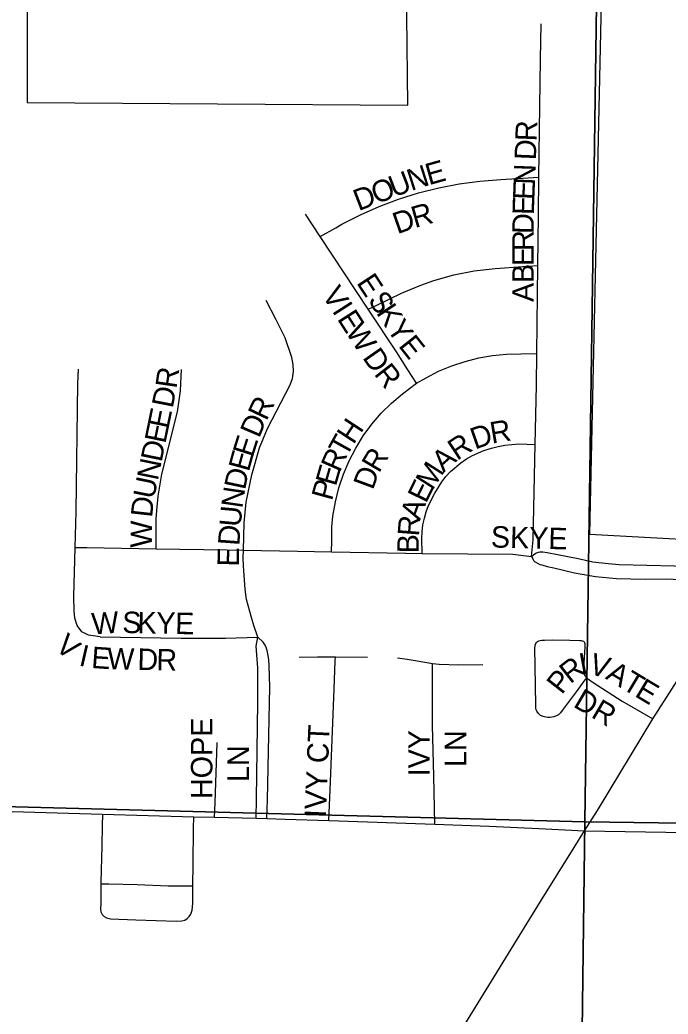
# Model space of a CAD drawing. Extents: x 1587405 to 1714697, y 1028970 to 1155083.
# Drawn here: x 1654947 to 1656457, y 1118270 to 1120584 of the extents above; entities that cross this region are included whole.
import ezdxf

# ---------------------------------------------------------------- set-up
doc = ezdxf.new("R2010")
doc.units = 0
for name, color, linetype in [('GM_X_City_Street', 7, 'Continuous'), ('GM_X_City_Street_Text', 7, 'Continuous'), ('GM_X_Corporation', 7, 'Continuous'), ('GM_X_Section', 7, 'Continuous')]:
    doc.layers.add(name, color=color, linetype=linetype)

msp = doc.modelspace()

# ---------------------------------------------------------------- linework, layer by layer
at = {"layer": 'GM_X_City_Street'}
for points in [[(1656155.9, 1120217.6), (1656160, 1120492.5), (1656160.9, 1120575)], [(1655646.7, 1120079.8), (1655683.2, 1120100.2), (1655697.4, 1120108.1), (1655740.4, 1120129.9), (1655784.2, 1120149.2), (1655829.4, 1120166.6), (1655875.8, 1120181.2), (1655922.9, 1120193.1), (1655970.5, 1120202.3), (1656018.7, 1120208.5), (1656067.1, 1120212.2), (1656130.8, 1120216.1), (1656155.9, 1120217.6)], [(1656153.4, 1120012.3), (1656154.7, 1120129.5), (1656155.9, 1120217.6)], [(1655646.7, 1120079.8), (1655612.3, 1120131.9)], [(1655758.5, 1119910.3), (1655646.7, 1120079.8)], [(1655758.5, 1119910.3), (1655778.5, 1119919.9), (1655836.3, 1119947.6), (1655880.8, 1119966.4), (1655911.2, 1119977.4), (1655957.8, 1119990.4), (1656005.5, 1119999.9), (1656053.8, 1120005.5), (1656118.2, 1120009.9), (1656153.4, 1120012.3)], [(1656151.2, 1119807), (1656153.4, 1120012.3)], [(1655468.1, 1119349.7), (1655469.6, 1119413), (1655474.2, 1119461.5), (1655487.3, 1119525.2), (1655505.5, 1119587.8), (1655523.8, 1119633), (1655576.7, 1119734), (1655582.2, 1119749.3), (1655584.4, 1119765.5), (1655584, 1119781.7), (1655580.9, 1119797.7), (1655565.2, 1119844), (1655543.1, 1119887.4), (1655521.1, 1119931)], [(1655871.1, 1119738.6), (1655850.8, 1119769.1), (1655824.1, 1119810.9), (1655758.5, 1119910.3)], [(1655871.1, 1119738.6), (1655893.2, 1119750.9), (1655922.5, 1119765.8), (1655952.9, 1119778.4), (1655984, 1119788.8), (1656015.8, 1119796.9), (1656047.9, 1119802.4), (1656080.5, 1119805.7), (1656113.9, 1119806.8), (1656151.2, 1119807)], [(1656147.3, 1119595.3), (1656150.5, 1119733.9), (1656151.2, 1119807)], [(1655076.5, 1119355.9), (1655078.9, 1119439.3), (1655082.5, 1119737.7), (1655083.6, 1119771)], [(1655264.8, 1119352.9), (1655264.8, 1119371.8), (1655264.7, 1119421.4), (1655266, 1119442.1), (1655269.6, 1119475.2), (1655278, 1119526.8), (1655314.3, 1119671.9), (1655321.4, 1119720.6), (1655323.9, 1119770.2)], [(1655673.3, 1119346), (1655673.8, 1119371.1), (1655674.2, 1119403.5), (1655676.1, 1119428.5), (1655682, 1119461.7), (1655690.3, 1119494.3), (1655700.9, 1119526.2), (1655714.3, 1119557.1), (1655729.7, 1119586.7), (1655747, 1119615.3), (1655766.9, 1119642.6), (1655789, 1119668.1), (1655812.9, 1119691.9), (1655838.5, 1119713.8), (1655871.1, 1119738.6)], [(1655884, 1119341.9), (1655883.3, 1119376.9), (1655883.9, 1119392.5), (1655886, 1119408.3), (1655889.2, 1119423.8), (1655893.4, 1119439.1), (1655899.1, 1119453.8), (1655913.7, 1119482.2), (1655930.3, 1119508.7), (1655939.4, 1119520.7), (1655949.8, 1119532.4), (1655974.1, 1119553.1), (1655987.1, 1119562), (1656001, 1119569.6), (1656028.1, 1119581.9), (1656045.5, 1119587), (1656061, 1119590.8), (1656076.6, 1119593.8), (1656109, 1119597.2), (1656128.6, 1119596.2), (1656147.3, 1119595.3)], [(1656138.8, 1119334.8), (1656142.3, 1119373.8), (1656147.3, 1119595.3)], [(1655134.4, 1119147.9), (1655107.3, 1119151.3), (1655091.8, 1119159.8), (1655080.6, 1119174.4), (1655075.7, 1119191.3), (1655074, 1119208.1), (1655073.4, 1119241.7), (1655076.5, 1119355.9)], [(1655076.5, 1119355.9), (1655103.5, 1119355.5), (1655264.8, 1119352.9)], [(1655264.8, 1119352.9), (1655430.5, 1119350.3), (1655468.1, 1119349.7)], [(1655501.2, 1119146.7), (1655491.9, 1119174.4), (1655486.7, 1119193), (1655475.3, 1119234.6), (1655471.9, 1119258.4), (1655467.9, 1119312.4), (1655467.7, 1119331.8), (1655468.1, 1119349.7)], [(1655468.1, 1119349.7), (1655593.9, 1119347.1), (1655673.3, 1119346)], [(1655673.3, 1119346), (1655846, 1119342.7), (1655884, 1119341.9)], [(1655884, 1119341.9), (1656095.6, 1119340), (1656138.8, 1119334.8)], [(1656138.8, 1119334.8), (1656144.1, 1119339.2), (1656145.5, 1119340.2), (1656148.5, 1119342.2), (1656150.2, 1119343.1), (1656152.4, 1119344.1), (1656154.8, 1119344.8), (1656157.8, 1119345.5), (1656161, 1119345.7), (1656164.9, 1119345.5), (1656175.4, 1119344.1), (1656247.3, 1119329.9), (1656281.8, 1119322.7), (1656317.5, 1119318.1), (1656342.5, 1119315.9), (1656472, 1119312.8), (1656503.6, 1119309.5), (1656527.9, 1119304.2), (1656551.9, 1119296.7), (1656579, 1119286.2), (1656615.4, 1119270.5)], [(1656138.8, 1119334.8), (1656140.7, 1119330.8), (1656142.7, 1119327.2), (1656144.1, 1119325.2), (1656145.2, 1119323.7), (1656147.1, 1119322), (1656152.3, 1119318.9), (1656158.2, 1119316.5), (1656162.4, 1119315), (1656175.1, 1119311.8), (1656190.5, 1119308.5), (1656238.8, 1119297.1), (1656287.6, 1119288.5), (1656336.9, 1119283.4), (1656403.1, 1119282.2), (1656452.6, 1119283.1), (1656485.2, 1119281.2), (1656501.3, 1119278.8), (1656517.3, 1119275), (1656533.1, 1119269.9), (1656545.1, 1119265), (1656597.4, 1119241.2)], [(1655134.4, 1119147.9), (1655322.7, 1119144.3), (1655426.1, 1119144.6), (1655501.2, 1119146.7)], [(1655497.6, 1118725.5), (1655498.3, 1118770.5), (1655501.9, 1118995.7), (1655501.2, 1119076), (1655497.5, 1119126.4), (1655501.2, 1119146.7)], [(1655522.8, 1118724.8), (1655523.7, 1118768.2), (1655529.2, 1119031.1), (1655527.6, 1119080.4), (1655526.8, 1119095.1), (1655525, 1119107.9), (1655523.4, 1119116.1), (1655521.1, 1119123), (1655518.7, 1119128.3), (1655513.6, 1119135.6), (1655501.2, 1119146.7)], [(1656266.7, 1119052.6), (1656263.2, 1119047.8), (1656242.9, 1119019.5), (1656210.5, 1118976.4), (1656205.9, 1118971.1), (1656201.2, 1118966.3), (1656196.9, 1118963.5), (1656191, 1118961.6), (1656186.1, 1118960.5), (1656181.7, 1118960.2), (1656176.6, 1118960.1), (1656172.1, 1118960.6), (1656165.7, 1118962), (1656159.8, 1118964.8), (1656154.9, 1118969.1), (1656151.4, 1118974.6), (1656149.7, 1118978.2), (1656149, 1118981.4), (1656148.8, 1118985.8), (1656148.9, 1118989.1), (1656147.5, 1119079.4), (1656146.8, 1119122.1), (1656147.1, 1119125.8), (1656147.6, 1119128.6), (1656149, 1119132), (1656150.7, 1119134.4), (1656153, 1119136.6), (1656155.9, 1119138.2), (1656159, 1119139.2), (1656162.5, 1119139.9), (1656165.6, 1119140.2), (1656168.8, 1119140.4), (1656188.1, 1119140.8), (1656228.3, 1119140), (1656250.9, 1119139.5), (1656254, 1119139.3), (1656257, 1119138.7), (1656259.4, 1119137.7), (1656261.4, 1119135.9), (1656262.2, 1119134.3), (1656262.6, 1119132.3), (1656262.9, 1119128.3), (1656262.9, 1119124.1), (1656259.4, 1119074.6), (1656259.4, 1119072.1), (1656259.6, 1119069.5), (1656259.8, 1119067.6), (1656260.3, 1119064.8), (1656260.8, 1119062.8), (1656261.6, 1119060.4), (1656262.6, 1119058.1), (1656264.2, 1119055.4), (1656265.4, 1119054), (1656266.7, 1119052.6)], [(1655598.1, 1119100.4), (1655640.3, 1119101.6), (1655682, 1119101.3)], [(1655666.7, 1118720.6), (1655669.8, 1118791.5), (1655678.9, 1119026), (1655681.6, 1119091.8), (1655682, 1119101.3)], [(1655682, 1119101.3), (1655757.2, 1119100.6)], [(1655826.6, 1119099), (1655849.3, 1119096), (1655904.2, 1119086.1), (1655908.5, 1119085.7)], [(1656421, 1118956.9), (1656510, 1119095.2)], [(1655913.8, 1118711.6), (1655911.4, 1118824.4), (1655908.1, 1118941.5), (1655908.5, 1119039.3), (1655908.5, 1119075.6), (1655908.5, 1119085.7)], [(1655908.5, 1119085.7), (1655923.8, 1119084), (1655969.7, 1119082.5), (1656025.5, 1119083)], [(1656266.7, 1119052.6), (1656269, 1119050.8), (1656282.4, 1119041.4), (1656349.5, 1118998.2), (1656421, 1118956.9)], [(1656261.9, 1118696.1), (1656292.1, 1118743.9), (1656421, 1118956.9)], [(1655400.9, 1118728.2), (1655402, 1118761.7), (1655406.6, 1118901.8)], [(1654767.9, 1118745.5), (1654876, 1118742.5), (1655139.9, 1118735.3)], [(1655139.9, 1118735.3), (1655139.1, 1118707.8), (1655138.3, 1118661.2), (1655136.3, 1118576.1), (1655136.3, 1118572.8)], [(1655139.9, 1118735.3), (1655352.5, 1118728.7)], [(1655350.3, 1118567.8), (1655350.8, 1118618.9), (1655351.9, 1118702.6), (1655352.5, 1118728.7)], [(1655352.5, 1118728.7), (1655400.9, 1118728.2)], [(1655400.9, 1118728.2), (1655497.6, 1118725.5)], [(1655497.6, 1118725.5), (1655522.8, 1118724.8)], [(1655522.8, 1118724.8), (1655564.9, 1118723.7), (1655666.7, 1118720.6)], [(1655666.7, 1118720.6), (1655913.8, 1118711.6)], [(1655913.8, 1118711.6), (1656040.5, 1118707.3), (1656155.4, 1118701.7), (1656261.9, 1118696.1)], [(1655899.8, 1118108.8), (1655971, 1118224.9), (1656160, 1118532), (1656237.9, 1118657.3), (1656261.9, 1118696.1)], [(1656261.9, 1118696.1), (1656499.2, 1118692.1), (1656700.5, 1118689.5), (1657010.5, 1118684.7)], [(1655136.3, 1118572.8), (1655135.7, 1118527), (1655135.3, 1118513.8), (1655136.3, 1118507.4), (1655139, 1118501.5), (1655143.5, 1118496.9), (1655149.2, 1118493.8), (1655158.7, 1118491.6), (1655217.7, 1118489), (1655312.2, 1118486.3), (1655324.2, 1118486.5), (1655331.6, 1118488.5), (1655337, 1118492), (1655341.7, 1118496.6), (1655345.2, 1118502.1), (1655348.4, 1118511.3), (1655349.7, 1118519.3), (1655350.1, 1118527.6), (1655350.2, 1118560.3), (1655350.3, 1118567.8)], [(1655136.3, 1118572.8), (1655154.7, 1118572.5), (1655220.3, 1118571.5), (1655292.4, 1118568.4), (1655322, 1118568.1), (1655350.3, 1118567.8)]]:
    msp.add_lwpolyline(points, dxfattribs=at)
at = {"layer": 'GM_X_Corporation'}
for points in [[(1656304.6, 1120803.9), (1656274.1, 1119387), (1656671.8, 1119365.1), (1656830.9, 1119621), (1657614.6, 1119465.9), (1657543.9, 1118676.8), (1658937.7, 1118659.7), (1658909.3, 1121318.3)], [(1654964.8, 1120642.1), (1654964.7, 1120391.2), (1655850.7, 1120385.1), (1655846.4, 1120801.7)]]:
    msp.add_lwpolyline(points, dxfattribs=at)
at = {"layer": 'GM_X_Section'}
for points in [[(1656339.6, 1124095.9), (1656263, 1118717.5), (1651255.5, 1118849.2), (1651252.7, 1118939.3), (1651349.7, 1124201.4)], [(1656513.6, 1124091.6), (1661797.4, 1123966), (1661837.5, 1123967.6), (1661639.2, 1118644.5), (1656263, 1118717.5), (1656339.6, 1124095.9)], [(1651255.5, 1118849.2), (1656263, 1118717.5), (1656195.7, 1113439), (1651152, 1113557.3), (1651155.1, 1113643.3)], [(1656263, 1118717.5), (1661639.2, 1118644.5), (1661579.6, 1113384), (1656195.7, 1113439)]]:
    msp.add_lwpolyline(points, close=True, dxfattribs=at)

# ---------------------------------------------------------------- texts
at = {"layer": 'GM_X_City_Street_Text'}
for s, rotation, p in [('R', 87.7404, (1656150.6, 1120300.6)), ('D', 87.7635, (1656148.9, 1120256.7)), ('E', 15.6601, (1655899.8, 1120198.8)), ('U', 21.014, (1655818, 1120170)), ('N', 17.7022, (1655858.4, 1120185.5)), ('N', 87.7478, (1656146.7, 1120199.5)), ('O', 21.083, (1655777, 1120154.2)), ('E', 87.7869, (1656145.3, 1120164.3)), ('D', 21.083, (1655735.9, 1120138.4)), ('E', 88.251, (1656144.2, 1120129.2)), ('D', 19.2643, (1655826.3, 1120084.7)), ('R', 15.9921, (1655867.1, 1120099)), ('D', 89.6721, (1656144, 1120085.6)), ('R', 89.9703, (1656144, 1120046.1)), ('E', 89.9727, (1656144, 1120010.9)), ('B', 89.994, (1656144, 1119971.3)), ('E', 303.3491, (1655729.9, 1119972)), ('V', 302.6472, (1655649.4, 1119943.6)), ('S', 303.3672, (1655756.5, 1119931.6)), ('A', 89.9781, (1656144, 1119927.3)), ('I', 302.6695, (1655673.2, 1119906.6)), ('E', 302.6762, (1655685.1, 1119888)), ('K', 303.377, (1655775.8, 1119902.1)), ('W', 302.9137, (1655704.2, 1119858.2)), ('Y', 303.6989, (1655800.2, 1119865.2)), ('E', 308.5416, (1655827.3, 1119824.8)), ('D', 304.938, (1655743.8, 1119797.7)), ('R', 81.7058, (1655312.1, 1119724.2)), ('R', 307.8643, (1655770.6, 1119759.4)), ('D', 78.9118, (1655303.2, 1119678.4)), ('R', 64.5972, (1655521.5, 1119648.6)), ('E', 78.3833, (1655293.3, 1119630.5)), ('D', 66.8186, (1655504.4, 1119608.6)), ('H', 56.7645, (1655724.2, 1119593.7)), ('R', 9.4424, (1656046.4, 1119597.4)), ('E', 78.3632, (1655286.2, 1119596)), ('D', 19.2436, (1656007, 1119583.5)), ('D', 78.3807, (1655277.4, 1119552.9)), ('E', 72.4635, (1655489.6, 1119563.9)), ('T', 60.9056, (1655707.5, 1119563.8)), ('R', 33.3466, (1655965.3, 1119556.9)), ('E', 74.685, (1655480.5, 1119530.4)), ('R', 66.2274, (1655692.1, 1119528.6)), ('R', 59.3694, (1655783.5, 1119527.1)), ('A', 41.6916, (1655933.9, 1119528.8)), ('N', 78.3815, (1655268.5, 1119509.8)), ('D', 78.1327, (1655471.6, 1119488.2)), ('E', 74.0546, (1655683.1, 1119496.5)), ('D', 69.6844, (1655769.2, 1119488)), ('M', 57.4366, (1655907.8, 1119487)), ('U', 78.6258, (1655259.8, 1119466.8)), ('P', 74.6514, (1655673.8, 1119462.7)), ('E', 63.9116, (1655893.1, 1119456.7)), ('N', 81.6659, (1655465.4, 1119445.4)), ('D', 83.6477, (1655255.1, 1119424.2)), ('U', 84.857, (1655461.5, 1119402.3)), ('A', 70.2727, (1655878.8, 1119416.7)), ('W', 89.7982, (1655255, 1119355.2)), ('R', 85.5268, (1655876.5, 1119380.6)), ('D', 85.7991, (1655458.3, 1119358.7)), ('SKYE', 358.4514, (1656043.6, 1119355.9)), ('B', 89.2471, (1655876, 1119341.9)), ('E', 89.153, (1655457.4, 1119311.1)), ('W', 4.3084, (1655116.4, 1119152.9)), ('S', 358.8897, (1655185.5, 1119156.8)), ('K', 358.8634, (1655220.7, 1119156.1)), ('Y', 358.8893, (1655264.7, 1119155.3)), ('E', 358.8799, (1655308.7, 1119154.4)), ('V', 320.4491, (1655027, 1119120.5)), ('I', 346.9359, (1655082.9, 1119081.6)), ('E', 355.9777, (1655112.7, 1119075.4)), ('W', 358.3585, (1655150.1, 1119072.8)), ('D', 358.7621, (1655220.8, 1119070.9)), ('R', 358.7673, (1655264.8, 1119069.9)), ('R', 38.0463, (1656228.8, 1119036.9)), ('I', 10.4423, (1656254.3, 1119058.8)), ('V', 342.8383, (1656269.6, 1119063.1)), ('A', 329.0362, (1656308.7, 1119051.4)), ('T', 329.0362, (1656346.5, 1119028.8)), ('P', 51.8483, (1656209.3, 1119011.5)), ('E', 329.0362, (1656376.7, 1119010.7)), ('DR', 329.5361, (1656233.6, 1118986.4)), ('HOPE', 90, (1655395.8, 1118770.1)), ('IVY CT', 87.5117, (1655659.8, 1118726.5)), ('IVY', 90, (1655901.8, 1118822.9)), ('LN', 90, (1655986.8, 1118844.9)), ('LN', 90, (1655480.8, 1118809.7))]:
    msp.add_text(s, height=50, rotation=rotation, dxfattribs=at).set_placement(p)

doc.saveas('drawing.dxf')
